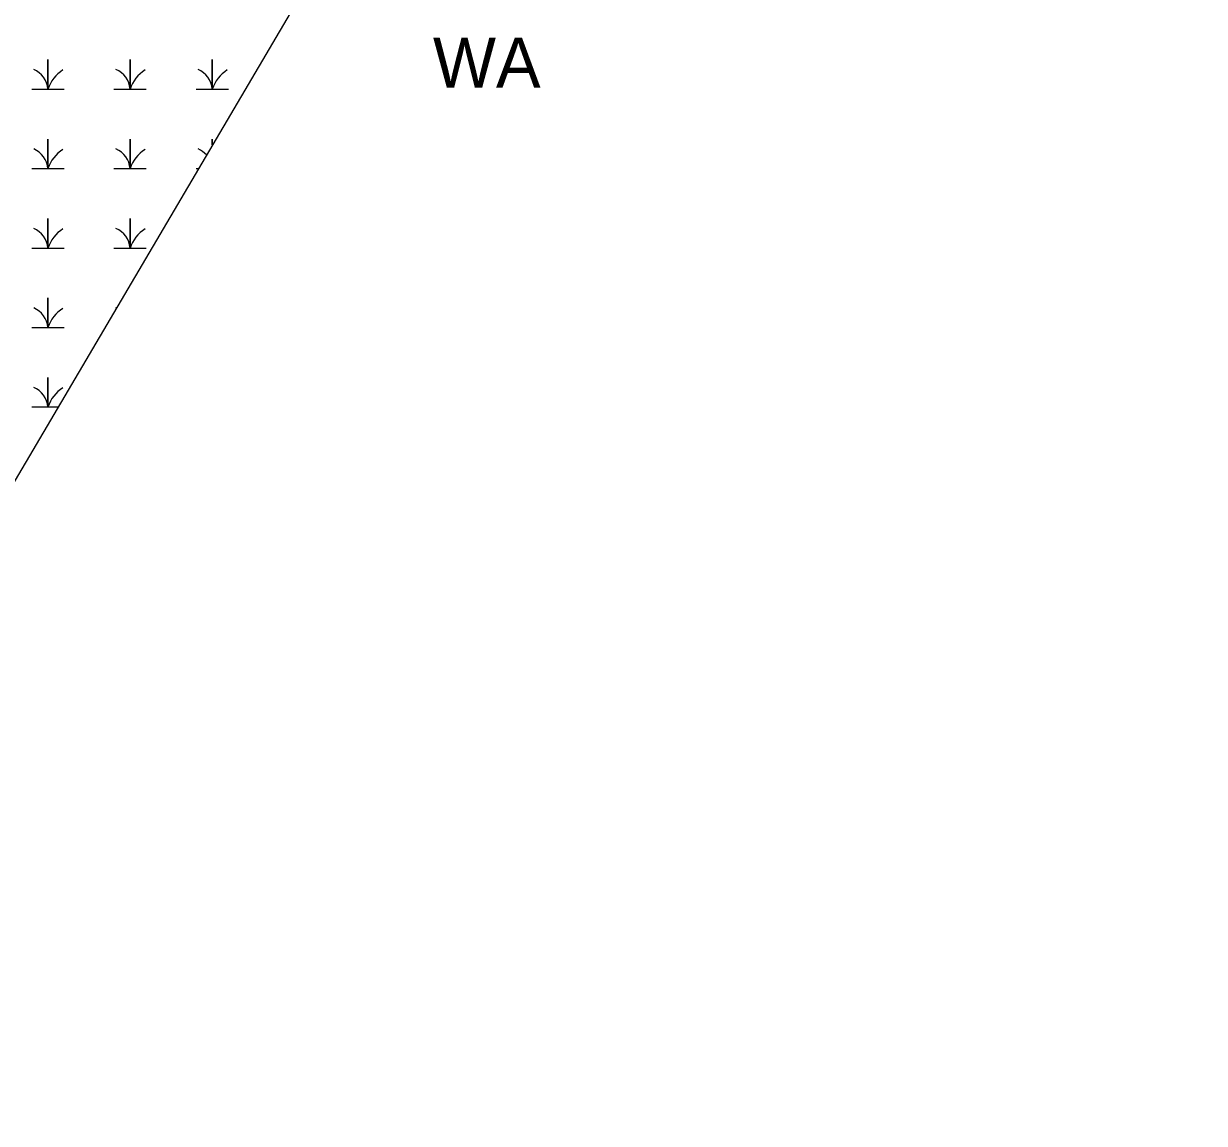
# Model space of a CAD drawing. Extents: x 2379288 to 2381905, y 330670 to 333511.
# Drawn here: x 2380217.6 to 2380453.9, y 331532.1 to 331752.4 of the extents above; entities that cross this region are included whole.
import ezdxf

# ---------------------------------------------------------------- set-up
doc = ezdxf.new("R2010")
doc.units = 0
for name, color, linetype in [('Default', 7, 'Continuous'), ('Exist Environmental Wetland Boundary Text', 7, 'Continuous'), ('Exist Hydro Swamp or Marsh', 7, 'Continuous')]:
    doc.layers.add(name, color=color, linetype=linetype)

msp = doc.modelspace()

# ---------------------------------------------------------------- linework, layer by layer
at = {"layer": 'Default'}
msp.add_lwpolyline([(2380453.94, 332065.55), (2379632.78, 330670.47), (2379288.07, 330873.37), (2380109.3, 332268.58)], dxfattribs=at)
at = {"layer": 'Exist Hydro Swamp or Marsh'}
msp.add_line((2380252.09, 331723.35), (2380252.52, 331723.35), dxfattribs=at)
for points in [[(2380219.19, 331739.27), (2380222.42, 331739.27), (2380222.42, 331745.19), (2380222.42, 331739.27), (2380225.64, 331739.27)], [(2380235.64, 331739.27), (2380238.87, 331739.27), (2380238.87, 331745.19), (2380238.87, 331739.27), (2380242.09, 331739.27)], [(2380252.09, 331739.27), (2380255.32, 331739.27), (2380255.32, 331745.19), (2380255.32, 331739.27), (2380258.54, 331739.27)], [(2380219.19, 331723.35), (2380222.42, 331723.35), (2380222.42, 331729.27), (2380222.42, 331723.35), (2380225.64, 331723.35)], [(2380235.64, 331723.35), (2380238.87, 331723.35), (2380238.87, 331729.27), (2380238.87, 331723.35), (2380242.09, 331723.35)], [(2380255.32, 331728.11), (2380255.32, 331729.27), (2380255.32, 331728.11)], [(2380219.19, 331707.43), (2380222.42, 331707.43), (2380222.42, 331713.35), (2380222.42, 331707.43), (2380225.64, 331707.43)], [(2380235.64, 331707.43), (2380238.87, 331707.43), (2380238.87, 331713.35), (2380238.87, 331707.43), (2380242.09, 331707.43)], [(2380219.19, 331691.52), (2380222.42, 331691.52), (2380222.42, 331697.43), (2380222.42, 331691.52), (2380225.64, 331691.52)], [(2380219.19, 331675.6), (2380222.42, 331675.6), (2380222.42, 331681.52), (2380222.42, 331675.6), (2380224.41, 331675.6)]]:
    msp.add_lwpolyline(points, dxfattribs=at)
for centre, radius, start, end in [((2380217.82, 331738.94), 4.61, 4.1403, 67.535), ((2380229.26, 331737), 7.21, 122.1274, 161.6222), ((2380234.27, 331738.94), 4.61, 4.1403, 67.535), ((2380245.71, 331737), 7.21, 122.1274, 161.6222), ((2380250.72, 331738.94), 4.61, 4.1403, 67.535), ((2380262.16, 331737), 7.21, 122.1274, 161.6222), ((2380217.82, 331723.02), 4.61, 4.1403, 67.535), ((2380229.26, 331721.08), 7.21, 122.1274, 161.6222), ((2380234.27, 331723.02), 4.61, 4.1403, 67.535), ((2380245.71, 331721.08), 7.21, 122.1274, 161.6222), ((2380250.72, 331723.02), 4.61, 42.0756, 67.535), ((2380217.82, 331707.1), 4.61, 4.1403, 67.535), ((2380229.26, 331705.16), 7.21, 122.1274, 161.6222), ((2380234.27, 331707.1), 4.61, 4.1403, 67.535), ((2380245.71, 331705.16), 7.21, 122.1274, 161.6222), ((2380217.82, 331691.18), 4.61, 4.1403, 67.535), ((2380229.26, 331689.24), 7.21, 122.1274, 161.6222), ((2380234.27, 331691.18), 4.61, 66.8529, 67.535), ((2380217.82, 331675.26), 4.61, 4.1403, 67.535), ((2380229.26, 331673.32), 7.21, 122.1274, 161.6222)]:
    msp.add_arc(centre, radius, start, end, dxfattribs=at)

# ---------------------------------------------------------------- texts
at = {"layer": 'Exist Environmental Wetland Boundary Text'}
msp.add_text('WA', height=10, dxfattribs=at).set_placement((2380299.5, 331739.59))

doc.saveas('drawing.dxf')
